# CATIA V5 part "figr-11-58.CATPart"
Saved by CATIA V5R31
Part number: Part1
Bounding box of the stored display mesh (mm): x -59.829 to 59.829, y -71.429 to 72.174, z -61 to 76
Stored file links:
  D:\PROJECTS\Project 2021\US EDITION\CATIA V5 6R 2021\Resources\Part Files\c11_catia_v5_6r2021_prt\figr-11-58.CATPart
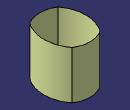
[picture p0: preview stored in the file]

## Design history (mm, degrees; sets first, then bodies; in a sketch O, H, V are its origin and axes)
Set1
  Extrude1: Element1 Sketch1, Lim1 76, Lim2 61, Direction xy-plane
Body1 (main body)
  Sketch1 on xy-plane, origin (0, 0, 0), H (0, 1, 0), V (-1, 0, 0)
    arc A1 centre (0, -40) radius 100 from (-60, 40) to (60, 40) cw
    point P2 (0, 60)
    point P3 (-60, 40)
    point P4 (60, 40)
    axis line L1 (-90, 0) -> (80, 0)
    point P6 (80, 0)
    point P7 (60, -40)
    point P8 (-60, -40)
    arc A2 centre (0, 40) radius 100 from (-60, -40) to (60, -40) ccw
    arc A3 centre (4.2857, 0) radius 75.7143 from (-60, 40) to (-60, -40) ccw
    arc A4 centre (0.3727, 0) radius 71.8012 from (60, -40) to (60, 40) ccw
    coincidence: A1 P2, P2 V, A3 P6
    horizontal: L1 H
    symmetry: P4 P7 L1, P3 P8 L1, A1 A2 L1
    tangency: A4 A3
  Sketch2 on xy-plane, origin (0, 0, 0), H (1, 0, 0), V (0, 1, 0)
    spline S1 through (80, 90) (60, 60) (70, 0) (50, -50) (50, -80)
    point P1 (70, 0)
    coincidence: P1 H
